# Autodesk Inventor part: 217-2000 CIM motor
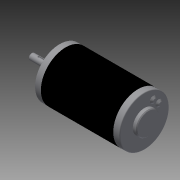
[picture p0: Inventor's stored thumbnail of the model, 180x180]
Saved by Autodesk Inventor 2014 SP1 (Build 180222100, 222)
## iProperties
Created: 2013-12
Part Number: 217-2000 CIM motor
Material: Generic
Document SubType Name: Modeling
Designer: Mech
Density: 3.57188 g/cm^3
Appearance: Default
Mass: 1279.13 g
Surface Area: 301.303 cm^2
Volume: 358.112 cm^3
Title: 217-2000.STEP
Description: STEP AP203
Creation Date: 2013-01-15
Sending System: SolidWorks 2012
Preprocessor: SwSTEP 2.0
Author: Mech
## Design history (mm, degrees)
node "217-20001"
node "Chamfer3"
node "Base1"
